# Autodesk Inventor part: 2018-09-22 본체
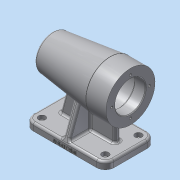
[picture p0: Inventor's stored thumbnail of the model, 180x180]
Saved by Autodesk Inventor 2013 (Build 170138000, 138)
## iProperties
Created: 2018-09
Part Number: 2018-09-22 본체
Material: 알루미늄 6061
Document SubType Name: Modeling
Designer: dgall
Density: 2.71 g/cm^3
Mass: 734.405 g
Surface Area: 664.48 cm^2
Volume: 270.998 cm^3
Author: dgall
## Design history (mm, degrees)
sketch "스케치1"
  geometry: L1 (-56, -35)-(56, -35); L2 (56, -35)-(56, 35); L3 (56, 35)-(-56, 35); L4 (-56, 35)-(-56, -35); L5 (-56, -35)-(56, 35); L6 (56, -35)-(-56, 35); 1 further point
  constraints: 12 end point, 2 midpoint, 2 parallel, 1 horizontal, 1 perpendicular
  dimensions: "d0" = 112 distance of L2.end L3.end; "d2" = 70 distance of L1.end L2.end
extrude "돌출1" new body sketch "스케치1" distance "d3" = 10; taper "d4" = 0 deg
sketch "스케치5"
  geometry: L1 (-56, 74)-(-56, 108); L2 (-56, 108)-(-28, 108); L3 (-28, 108)-(52.27, 98.144); L4 (56, 74)-(-56, 74); L5 (0, 0)-(0, 74); A1 r 80 centre (-24, 74) between (56, 74) and (52.27, 98.144)
  constraints: 10 end point, 2 parallel, 2 point on circle, 1 centre point, 1 midpoint, 1 perpendicular, 1 vertical
  dimensions: "d29" = 112 distance of L4.start L1.start; "d30" = 34 distance of L1.start L1.end; "d31" = 28 distance of L1.end L2.end; "d32" = 7 deg angle of L2 L3; "d33" = 80 radius of A1; "d39" = 74 distance of L5.start L5.end; "d42" = 24.14412 distance from line of L4 L3.end
revolve "회전1" sketch "스케치5" stored, may be unused: angle "d34" = 90 deg
fillet "모깎기1" dims "d35" = 3
fillet "모깎기2" dims "d36" = 3
fillet "모깎기3" dims "d37" = 12
sketch "스케치7"
  geometry: L1 (38, 10)-(21.975, 69.806); L2 (-38, 10)-(-38, 69.806); L3 (-38, 69.806)-(21.975, 69.806); L4 (38, 10)-(-38, 10); L5 (44, 10)-(56, 10) reference; L6 (-56, 10)-(-56, 0) reference; L7 (0, 0)-(0, 10); L8 (-44, 10)-(44, 10) reference
  constraints: 10 end point, 2 midpoint, 1 perpendicular
  dimensions: "d97" = 105 deg angle of L5 L1; "d98" = 76 distance of L1.start L2.start; "d99" = 18 distance from line of L2.start L6; "d100" = 59.80623 distance of L2.start L2.end; "d101" = 59.97497 distance of L2.end L1.end
extrude "돌출5" join sketch "스케치7" stored distance "d51" = 8; taper "d52" = 0 deg
sketch "스케치10"
  geometry: L1 (-4, 10)-(4, 10) reference; L2 (-10.263, 75.216)-(0, 75.216); L3 (0, 75.216)-(0, 10); L4 (-35, 0)-(-35, 10) reference; L5 (23, 0)-(-23, 0) reference; L6 (23, 10)-(-23, 10) reference; L7 (-35, 10)-(-23, 10) reference; L8 (0, 10)-(-34, 10); L9 (-34, 10)-(-10.263, 75.216); 1 further point
  constraints: 8 end point, 3 midpoint, 2 point on line, 1 perpendicular
  dimensions: "d96" = 10.26345 distance of L2.start L2.end; "d107" = 1 distance of L8.end L4.end; "d108" = 70 deg angle of L9 L7
extrude "돌출6" join sketch "스케치10" stored distance "d109" = 8; taper "d110" = 0 deg
node "작업 평면1"
fillet "모깎기6" dims "d112" = 3
fillet "모깎기7" dims "d113" = 3
sketch "스케치11"
  geometry: L1 (0, 0)-(0, 74); L2 (-56, 108)-(-56, 40) reference; L3 (-56, 74)-(50, 74); L4 (43, 90)-(43, 91.5); L5 (43, 91.5)-(25, 91.5); L6 (25, 91.5)-(25, 95); L7 (25, 95)-(13, 95); L8 (13, 95)-(13, 98); L9 (13, 98)-(-41, 98); L10 (-41, 98)-(-41, 95); L11 (-41, 95)-(-56, 95); L12 (43, 90)-(47, 90); L13 (47, 90)-(47, 84.5); L14 (47, 84.5)-(50, 84.5); L15 (50, 84.5)-(50, 74); L16 (-56, 95)-(-56, 74)
  constraints: 30 end point, 4 perpendicular, 2 parallel, 1 collinear, 1 midpoint, 1 point on line, 1 vertical
  dimensions: "d114" = 74 distance of L1.start L1.end; "d115" = 21 distance between parallel lines of L3 L11; "d116" = 15 distance between parallel lines of L10 L2; "d117" = 24 distance between parallel lines of L3 L9; "d118" = 54 distance between parallel lines of L10 L8; "d119" = 21 distance between parallel lines of L3 L7; "d120" = 12 distance from line of L8.end L6; "d121" = 18 distance between parallel lines of L6 L4; "d122" = 17.5 distance between parallel lines of L3 L5; "d123" = 10.5 distance of L14.end L3.end; "d124" = 16 distance between parallel lines of L3 L12; "d125" = 4 distance between parallel lines of L13 L4; "d126" = 3 distance between parallel lines of L15 L13
revolve "회전2" sketch "스케치11" stored, may be unused: angle "d127" = 90 deg
fillet "모깎기8" dims "d128" = 3
fillet "모깎기9" dims "d129" = 3
fillet "모깎기10" dims "d130" = 0.3
fillet "모깎기11" dims "d131" = 0.3
fillet "모깎기12" dims "d132" = 0.3
chamfer "모따기1" distance "d133" = 1; stored, may be unused: second distance "d134" = 2, angle "d135" = 45 deg
sketch "스케치12"
  geometry: C1 r 34 at (0, 0) reference; C2 r 22 at (0, 0) reference; A1 r 26 centre (0, 0) between (-26, 0) and (0, -26); 3 further points
  constraints: 4 point on circle, 2 horizontal alignment, 2 vertical alignment, 1 centre point, 1 coincident
  dimensions: "d136" = 52 diameter of A1
hole "구멍5" sketch "스케치12" at (-26, 0), (0, -26), (26, 0), (0, 26) diameter "d138" = 3.242; stored, may be unused: countersink angle "d142" = 90 deg, drill point angle "d144" = 118 deg; dims "d139" = 8, "d140" = 9.5, "d141" = 5.4, "d143" = 11
hole "구멍6" diameter "d147" = 5.5; stored, may be unused: countersink angle "d151" = 90 deg, drill point angle "d153" = 118 deg; dims "d145" = 10, "d146" = 10, "d148" = 8, "d149" = 9.5, "d150" = 5.4, "d152" = 11
hole "구멍7" diameter "d156" = 5.5; stored, may be unused: countersink angle "d160" = 90 deg, drill point angle "d162" = 118 deg; dims "d154" = 10, "d155" = 10, "d157" = 8, "d158" = 9.5, "d159" = 5.4, "d161" = 11
hole "구멍8" diameter "d165" = 5.5; stored, may be unused: countersink angle "d169" = 90 deg, drill point angle "d171" = 118 deg; dims "d163" = 10, "d164" = 10, "d166" = 8, "d167" = 9.5, "d168" = 5.4, "d170" = 11
hole "구멍9" diameter "d174" = 5.5; stored, may be unused: countersink angle "d178" = 90 deg, drill point angle "d180" = 118 deg; dims "d172" = 10, "d173" = 10, "d175" = 8, "d176" = 9.5, "d177" = 5.4, "d179" = 11
sketch "스케치13"
  geometry: L1 (100, 0)-(100, 7) reference; 2 further points
  constraints: 1 other
  dimensions: "d181" = 3 distance of point (44, 0) point (44, 3); "d182" = 56 distance from line of L1 point (44, 3)
feature "엠보싱1" sketch "스케치13" dims "d0" = 112, "d2" = 70, "d36" = 3, "d183" = 0.5, "d184" = 0
node "솔리드1"
mirror "대칭1"
other parameters: "d5" = 8, "d7" = 8, "d111" = 0
